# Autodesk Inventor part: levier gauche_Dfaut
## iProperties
Created: 2006-03
Part Number: levier gauche_Dfaut
Document SubType Name: Modeling
Designer: Flavien MARTY
Author: Flavien MARTY
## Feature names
1. Base1
